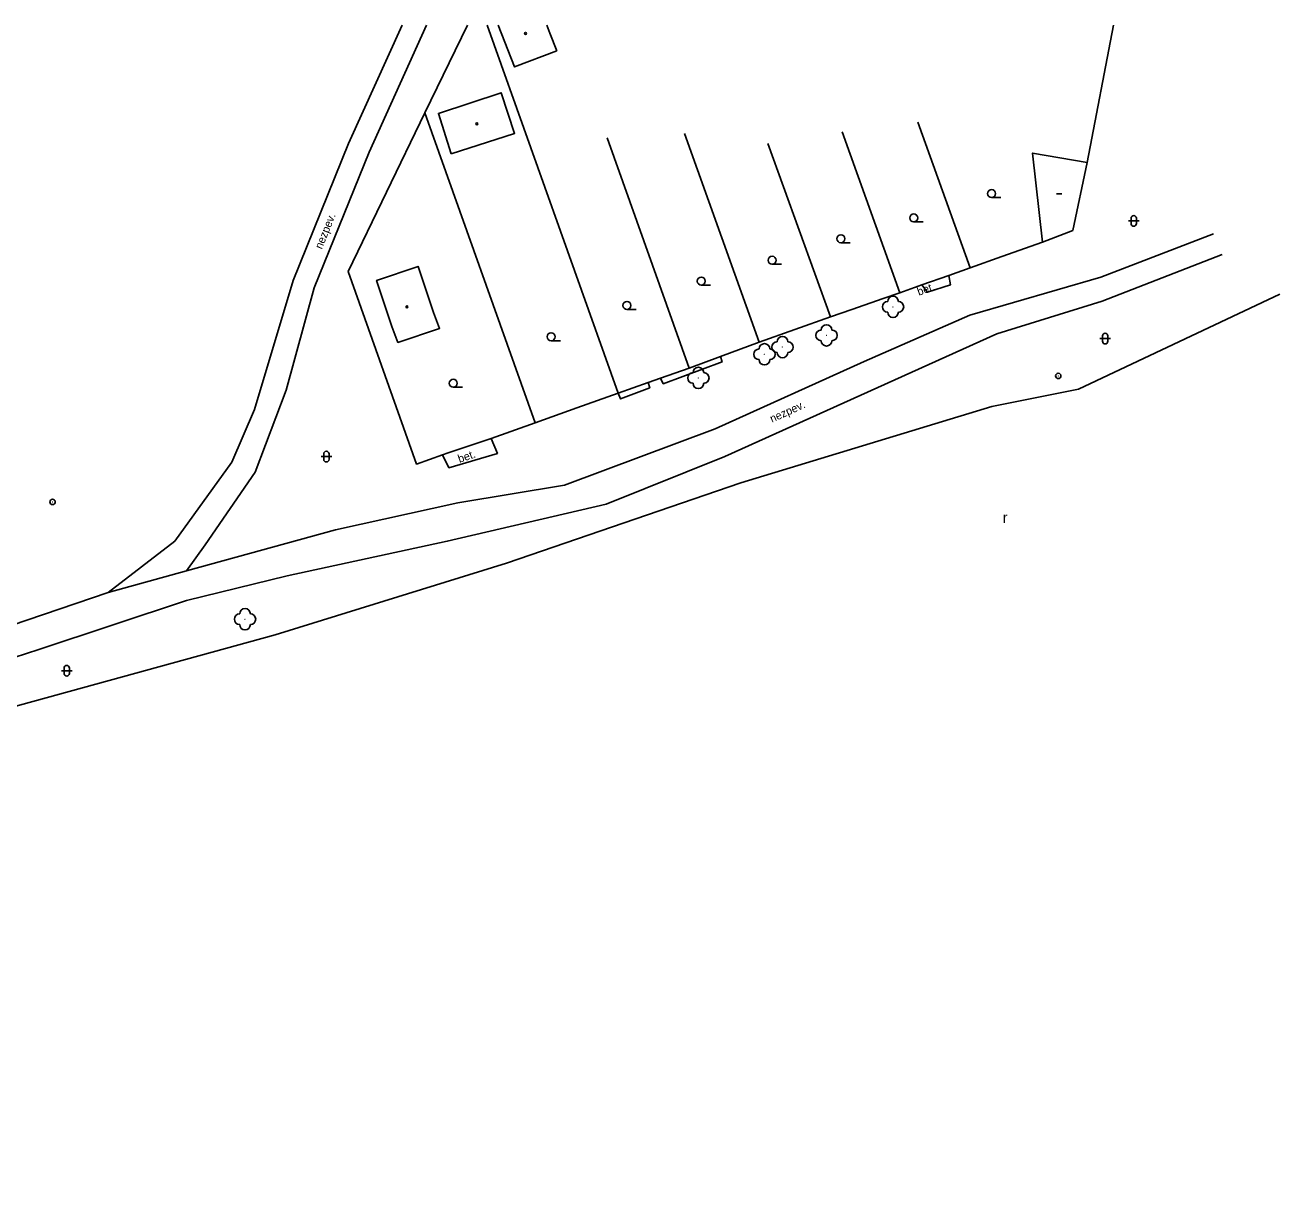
# Model space of a CAD drawing. Extents: x -762269 to -761395, y -1155167 to -1154999.
# Drawn here: x -761512.9 to -761395.4, y -1155108.4 to -1155000 of the extents above; entities that cross this region are included whole.
import ezdxf

# ---------------------------------------------------------------- set-up
doc = ezdxf.new("R2010")
doc.units = 0
for name, color, linetype in [('Vrstva 10', 7, 'Continuous'), ('Vrstva 11', 7, 'Continuous'), ('Vrstva 14', 7, 'Continuous'), ('Vrstva 3', 7, 'Continuous'), ('Vrstva 4', 7, 'Continuous'), ('Vrstva 5', 7, 'Continuous'), ('Vrstva 8', 7, 'Continuous'), ('Vrstva 9', 7, 'Continuous')]:
    doc.layers.add(name, color=color, linetype=linetype)

msp = doc.modelspace()

# ---------------------------------------------------------------- linework, layer by layer
at = {"layer": 'Vrstva 10'}
for points in [[(-761505.16, -1155053.16), (-761498.93, -1155048.33), (-761493.58, -1155040.93), (-761491.46, -1155036), (-761487.83, -1155023.93), (-761482.64, -1155011.09), (-761477.62, -1155000)], [(-761497.81, -1155051.11), (-761496.08, -1155048.69), (-761491.4, -1155041.88), (-761488.5, -1155034.2), (-761485.86, -1155024.62), (-761480.72, -1155011.91), (-761475.33, -1155000)], [(-761497.81, -1155051.11), (-761483.85, -1155047.28), (-761472.39, -1155044.75), (-761462.41, -1155043.08), (-761448.29, -1155037.83), (-761434.35, -1155031.52), (-761424.43, -1155027.18), (-761412.15, -1155023.6), (-761401.61, -1155019.54)], [(-761567.61, -1155096.85), (-761561.45, -1155084.61), (-761558.11, -1155079.93), (-761555.68, -1155077.57), (-761545.77, -1155070.2), (-761536.89, -1155066.67), (-761526.7, -1155063.35), (-761511.65, -1155058.47), (-761497.83, -1155053.9), (-761488.39, -1155051.58), (-761473.39, -1155048.35), (-761458.51, -1155044.87), (-761447.39, -1155040.4), (-761421.92, -1155028.91), (-761412.03, -1155025.85), (-761400.79, -1155021.48)], [(-761428.94, -1155024.34), (-761428.39, -1155025.02), (-761426.25, -1155024.33), (-761426.41, -1155023.44)], [(-761473.84, -1155040.26), (-761473.24, -1155041.46), (-761468.7, -1155040.11), (-761469.29, -1155038.72)], [(-761570.71, -1155094.75), (-761566.2, -1155086.96), (-761559.93, -1155078.65), (-761556.76, -1155074.72), (-761552.56, -1155070.73), (-761542.82, -1155065.77), (-761528.4, -1155061.2), (-761514.25, -1155056.23), (-761505.16, -1155053.16), (-761497.81, -1155051.11)]]:
    msp.add_lwpolyline(points, dxfattribs=at)
at = {"layer": 'Vrstva 11'}
msp.add_lwpolyline([(-761546.76, -1155108.35), (-761555.26, -1155091.77), (-761557.25, -1155082.57), (-761549.68, -1155076.73), (-761534.66, -1155069.56), (-761513.47, -1155063.7), (-761489.52, -1155057.1), (-761467.83, -1155050.4), (-761445.88, -1155042.87), (-761422.37, -1155035.73), (-761414.26, -1155034.1), (-761395.39, -1155025.2)], dxfattribs=at)
for centre in [(-761431.63, -1155026.39), (-761437.86, -1155029.06), (-761441.99, -1155030.16), (-761443.68, -1155030.83), (-761449.87, -1155033.05), (-761492.34, -1155055.65)]:
    msp.add_circle(centre, 0.0005, dxfattribs=at)
for centre, start, end in [((-761432.13, -1155026.39), 89.99999, 269.99999), ((-761431.63, -1155025.89), 0, 179.99999), ((-761431.13, -1155026.39), 270, 89.99999), ((-761431.63, -1155026.89), 179.99999, 359.99999), ((-761437.86, -1155028.56), 0, 179.99999), ((-761441.99, -1155029.66), 0, 179.99999), ((-761438.36, -1155029.06), 89.99999, 269.99999), ((-761437.36, -1155029.06), 270, 89.99999), ((-761444.18, -1155030.83), 89.99999, 269.99999), ((-761443.68, -1155030.33), 0, 179.99999), ((-761443.18, -1155030.83), 270, 89.99999), ((-761442.49, -1155030.16), 89.99999, 269.99999), ((-761441.99, -1155030.66), 179.99999, 359.99999), ((-761441.49, -1155030.16), 270, 89.99999), ((-761437.86, -1155029.56), 179.99999, 359.99999), ((-761443.68, -1155031.33), 179.99999, 359.99999), ((-761450.37, -1155033.05), 89.99999, 269.99999), ((-761449.87, -1155032.55), 0, 179.99999), ((-761449.37, -1155033.05), 270, 89.99999), ((-761449.87, -1155033.55), 179.99999, 359.99999), ((-761492.84, -1155055.65), 89.99999, 269.99999), ((-761492.34, -1155055.15), 0, 179.99999), ((-761491.84, -1155055.65), 270, 89.99999), ((-761492.34, -1155056.15), 179.99999, 359.99999)]:
    msp.add_arc(centre, 0.5, start, end, dxfattribs=at)
at = {"layer": 'Vrstva 3'}
for p, q in [((-761422.4, -1155016.155), (-761421.525, -1155016.155)), ((-761429.69, -1155018.435), (-761428.815, -1155018.435)), ((-761409.58, -1155018.34), (-761408.58, -1155018.34)), ((-761409.33, -1155018.59), (-761409.33, -1155018.09)), ((-761408.83, -1155018.59), (-761408.83, -1155018.09)), ((-761436.52, -1155020.385), (-761435.645, -1155020.385)), ((-761442.96, -1155022.405), (-761442.085, -1155022.405)), ((-761449.6, -1155024.355), (-761448.725, -1155024.355)), ((-761456.56, -1155026.635), (-761455.685, -1155026.635)), ((-761412.26, -1155029.36), (-761411.26, -1155029.36)), ((-761412.01, -1155029.61), (-761412.01, -1155029.11)), ((-761411.51, -1155029.61), (-761411.51, -1155029.11)), ((-761463.66, -1155029.565), (-761462.785, -1155029.565)), ((-761472.83, -1155033.925), (-761471.955, -1155033.925)), ((-761485.22, -1155040.42), (-761484.22, -1155040.42)), ((-761484.97, -1155040.67), (-761484.97, -1155040.17)), ((-761484.47, -1155040.67), (-761484.47, -1155040.17)), ((-761509.54, -1155060.47), (-761508.54, -1155060.47)), ((-761509.29, -1155060.72), (-761509.29, -1155060.22)), ((-761508.79, -1155060.72), (-761508.79, -1155060.22))]:
    msp.add_line(p, q, dxfattribs=at)
for centre in [(-761422.4, -1155015.78), (-761429.69, -1155018.06), (-761436.52, -1155020.01), (-761442.96, -1155022.03), (-761449.6, -1155023.98), (-761456.56, -1155026.26), (-761463.66, -1155029.19), (-761472.83, -1155033.55)]:
    msp.add_circle(centre, 0.375, dxfattribs=at)
for centre, start, end in [((-761409.08, -1155018.09), 0, 179.99999), ((-761409.08, -1155018.59), 179.99999, 359.99999), ((-761411.76, -1155029.11), 0, 179.99999), ((-761411.76, -1155029.61), 179.99999, 359.99999), ((-761484.72, -1155040.17), 0, 179.99999), ((-761484.72, -1155040.67), 179.99999, 359.99999), ((-761509.04, -1155060.22), 0, 179.99999), ((-761509.04, -1155060.72), 179.99999, 359.99999)]:
    msp.add_arc(centre, 0.25, start, end, dxfattribs=at)
at = {"layer": 'Vrstva 4'}
msp.add_lwpolyline([(-761413.45, -1155012.87), (-761418.56, -1155011.99), (-761417.64, -1155020.33), (-761414.79, -1155019.23), (-761413.45, -1155012.87)], dxfattribs=at)
at = {"layer": 'Vrstva 5'}
for points in [[(-761463.14, -1155002.4), (-761467.1, -1155003.91), (-761468.61, -1155000)], [(-761464.06, -1155000), (-761463.77, -1155000.75), (-761463.14, -1155002.4)], [(-761473.02, -1155012.07), (-761474.22, -1155008.27), (-761468.33, -1155006.34), (-761467.09, -1155010.15), (-761473.02, -1155012.07)], [(-761474.69, -1155026.92), (-761474.11, -1155028.41), (-761478.01, -1155029.72), (-761478.59, -1155028.22), (-761480.01, -1155023.91), (-761476.13, -1155022.6), (-761474.69, -1155026.92)]]:
    msp.add_lwpolyline(points, dxfattribs=at)
at = {"layer": 'Vrstva 8'}
msp.add_line((-761416.33, -1155015.81), (-761415.83, -1155015.81), dxfattribs=at)
for centre in [(-761466.06, -1155000.78), (-761470.62, -1155009.24), (-761477.17, -1155026.39)]:
    msp.add_circle(centre, 0.0875, dxfattribs=at)
at = {"layer": 'Vrstva 9'}
for points in [[(-761475.49, -1155008.23), (-761471.51, -1155000)], [(-761469.64, -1155000), (-761457.38, -1155034.46)], [(-761413.45, -1155012.87), (-761410.98, -1155000)], [(-761473.31, -1155040.07), (-761473.84, -1155040.26), (-761476.26, -1155041.12), (-761482.67, -1155023.09), (-761475.49, -1155008.23)], [(-761475.49, -1155008.23), (-761465.17, -1155037.25)], [(-761429.3, -1155009.08), (-761424.4, -1155022.73)], [(-761458.41, -1155010.57), (-761450.72, -1155032.14)], [(-761451.16, -1155010.15), (-761444.17, -1155029.71)], [(-761436.41, -1155010), (-761431.01, -1155025.09)], [(-761443.36, -1155011.1), (-761437.5, -1155027.34)], [(-761421.45, -1155021.68), (-761417.64, -1155020.33)], [(-761424.4, -1155022.73), (-761421.45, -1155021.68)], [(-761428.94, -1155024.34), (-761426.41, -1155023.44)], [(-761426.41, -1155023.44), (-761424.4, -1155022.73)], [(-761431.01, -1155025.09), (-761428.94, -1155024.34)], [(-761435.48, -1155026.63), (-761432.57, -1155025.6)], [(-761432.57, -1155025.6), (-761431.01, -1155025.09)], [(-761437.5, -1155027.34), (-761435.48, -1155026.63)], [(-761444.17, -1155029.71), (-761437.5, -1155027.34)], [(-761447.79, -1155031.05), (-761444.17, -1155029.71)], [(-761453.41, -1155033.08), (-761453.16, -1155033.6), (-761447.65, -1155031.54), (-761447.79, -1155031.05)], [(-761450.72, -1155032.14), (-761447.79, -1155031.05)], [(-761453.41, -1155033.08), (-761450.72, -1155032.14)], [(-761457.38, -1155034.46), (-761457.17, -1155035.02), (-761454.42, -1155033.97), (-761454.57, -1155033.48)], [(-761457.38, -1155034.46), (-761454.57, -1155033.48)], [(-761454.57, -1155033.48), (-761453.41, -1155033.08)], [(-761461.27, -1155035.86), (-761457.38, -1155034.46)], [(-761465.17, -1155037.25), (-761461.27, -1155035.86)], [(-761469.29, -1155038.72), (-761465.17, -1155037.25)], [(-761473.31, -1155040.07), (-761469.29, -1155038.72)]]:
    msp.add_lwpolyline(points, dxfattribs=at)
for centre, radius in [((-761416.15, -1155032.86), 0.25), ((-761416.15, -1155032.86), 0.0005), ((-761510.37, -1155044.66), 0.25), ((-761510.37, -1155044.66), 0.0005)]:
    msp.add_circle(centre, radius, dxfattribs=at)

# ---------------------------------------------------------------- texts
at = {"layer": 'Vrstva 14'}
for s, rotation, p in [('nezpev.', 67.99116, (-761485.14, -1155021.04)), ('bet.', 19.58206, (-761429.22, -1155025.35)), ('nezpev.', 24.35409, (-761442.97, -1155037.25)), ('bet.', 18.69898, (-761472.25, -1155041.01))]:
    msp.add_text(s, height=0.75, rotation=rotation, dxfattribs=at).set_placement(p)
at = {"layer": 'Vrstva 3'}
msp.add_text('r', height=1, dxfattribs=at).set_placement((-761421.348, -1155046.622))

doc.saveas('drawing.dxf')
